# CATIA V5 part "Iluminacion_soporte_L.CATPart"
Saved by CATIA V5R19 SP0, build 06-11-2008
Part number: Iluminación_soporte_L
Bounding box of the stored display mesh (mm): x -75 to 75, y -15 to 1850, z 0 to 1665
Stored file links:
  C:\Users\Fran Robles\Documents\My Dropbox\DOCS ESI\Aernnova\Industrializacion 3D\Modelos 3d\Objetos_varios\Iluminacion_soporte_L.CATPart
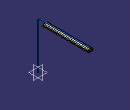
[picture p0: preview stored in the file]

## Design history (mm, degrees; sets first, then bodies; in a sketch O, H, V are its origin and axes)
Body1 (main body)
  Sketch1 on xy-plane, origin (0, 0, 0), H (1, 0, 0), V (0, 1, 0)
    circle A1 centre (0, 0) radius 15
    radius A1 = 15
  Sketch2 on yz-plane, origin (0, 0, 0), H (0, 1, 0), V (0, 0, 1)
    line L1 (0, 0) -> (0, 1574.5868)
    point P1 (0, 1650)
    line L2 (75.4132, 1650) -> (1850, 1650)
    point P2 (1850, 1650)
    arc A1 centre (75.4132, 1574.5868) radius 75.4132 from (75.4132, 1650) to (0, 1574.5868) ccw
    distance P1 P2 = 1850
    distance O P1 = 1650
    radius A1 = 75.4132
    radius A1 = 75.4132 (reference)
    vertical: L1 V
    horizontal: L2 H
    coincidence: L2 P1, L1 P1
    tangency: A1 L2, A1 L1
  Rib1: profile Sketch1, centre curve Sketch2
Body2
  Sketch3 on face of Rib1, origin (0, 1850, 0), H (-1, 0, 0), V (0, 0, 1)
    reference projected circle E1 centre (0, 1650) radius 15 from face of Rib1
    point P1 (0, 1609)
    line L1 (75, 1634) -> (75, 1584)
    line L2 (75, 1584) -> (-75, 1584)
    line L3 (-75, 1584) -> (-75, 1634)
    line L4 (-75, 1634) -> (75, 1634)
    distance E1 L4 = 1
    length L1 = 50
    length L2 = 150
    coincidence: P1 V
    vertical: L1 V, L3 V
    horizontal: L2 H, L4 H
    equidistance: L1 L3 P1, L2 L4 P1
  Pad1: profile Sketch3, direction (0, -1, 0), length 1600
  Fillet1: radius 20, on edge [face of Pad1 from Sketch3.L4 | start face of Pad1]; edge [face of Pad1 from Sketch3.L1 | face of Pad1 from Sketch3.L4]; edge [face of Pad1 from Sketch3.L4 | face of Pad1 from Sketch3.L3]; edge [end face of Pad1 | face of Pad1 from Sketch3.L4]
Body3
  Sketch4 on start face of Pad1, origin (0, 1850, 0), H (-1, 0, 0), V (0, 0, 1)
    line L1 (-75, 1584) -> (75, 1584)
    line L2 (75, 1584) -> (75, 1534)
    line L3 (75, 1534) -> (-75, 1534)
    line L4 (-75, 1534) -> (-75, 1584)
    length L2 = 50
    horizontal: L1 H, L3 H
    vertical: L2 V, L4 V
  Pad2: profile Sketch4, direction (0, -1, 0), up to end face of Pad1
  Fillet2: radius 20, on edge [face of Pad2 from Sketch4.L4 | face of Pad2 from Sketch4.L3]; edge [face of Pad2 from Sketch4.L3 | start face of Pad2]; edge [face of Pad2 from Sketch4.L3 | face of Pad2 from Sketch4.L2]; edge [face of Pad2 from Sketch4.L3 | end face of Pad2]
